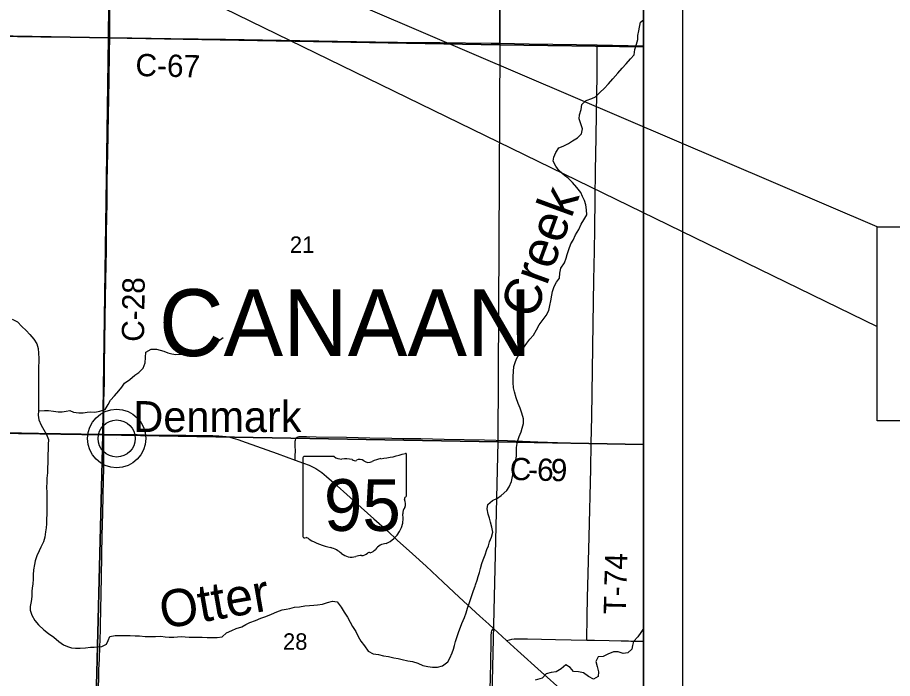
# Model space of a CAD drawing. Extents: x 0 to 45.9, y 0 to 22.
# Drawn here: x 7.305 to 9.535, y 15.053 to 16.738 of the extents above; entities that cross this region are included whole.
import ezdxf

# ---------------------------------------------------------------- set-up
doc = ezdxf.new("R2010")
doc.units = 0
for name, color, linetype in [('Default', 7, 'Continuous'), ('GM_X_County_Road', 7, 'Continuous'), ('GM_X_County_Road_Text', 7, 'Continuous'), ('GM_X_Minor_River', 7, 'Continuous'), ('GM_X_Minor_River_Text', 7, 'Continuous'), ('GM_X_Section', 7, 'Continuous'), ('GM_X_Section_Text', 7, 'Continuous'), ('GM_X_State_Location', 7, 'Continuous'), ('GM_X_State_Route', 7, 'Continuous'), ('GM_X_State_Shield', 7, 'Continuous'), ('GM_X_Township_Road', 7, 'Continuous'), ('GM_X_Township_Road_Text', 7, 'Continuous'), ('GM_X_Township_Text', 7, 'Continuous'), ('GM_X_Unincorporated', 7, 'Continuous'), ('GM_X_Unincorporated_Location', 7, 'Continuous'), ('GM_X_Unincorporated_Text', 7, 'Continuous'), ('SH_Border', 7, 'Continuous'), ('SH_Cut_Line', 7, 'Continuous'), ('SH_Text', 7, 'Continuous')]:
    doc.layers.add(name, color=color, linetype=linetype)

msp = doc.modelspace()

# ---------------------------------------------------------------- linework, layer by layer
at = {"layer": 'Default'}
msp.add_lwpolyline([(8.9, 14.1), (8.9, 19.7611)], dxfattribs=at)
for points in [[(8.9, 16.6634), (8.9, 17.6782), (8.5357, 17.6824), (8.5339, 16.6685)], [(8.9, 15.6495), (8.9, 16.6634), (8.5339, 16.6685), (8.5286, 15.6561)], [(8.9, 14.6398), (8.9, 15.6495), (8.5286, 15.6561), (8.5052, 14.6503)]]:
    msp.add_lwpolyline(points, close=True, dxfattribs=at)
at = {"layer": 'GM_X_County_Road'}
msp.add_line((8.7826, 16.6683), (8.9, 16.666), dxfattribs=at)
for points in [[(7.5398, 16.6872), (7.5398, 16.695), (7.5401, 16.7448), (7.5405, 16.7976), (7.5408, 16.8255), (7.5412, 16.8721), (7.5414, 16.925), (7.5417, 16.9716), (7.5421, 17.0244), (7.5424, 17.0648), (7.5425, 17.1145), (7.543, 17.1829), (7.5432, 17.2077), (7.5434, 17.2792), (7.5436, 17.3382), (7.5438, 17.3693), (7.5443, 17.4097), (7.5448, 17.4625), (7.5452, 17.5153), (7.5452, 17.5681), (7.5461, 17.6707), (7.5458, 17.698)], [(8.5341, 16.6724), (8.5341, 16.6809), (8.534, 16.7088), (8.5347, 16.8674), (8.5349, 16.9637), (8.5352, 17.116), (8.5351, 17.1813), (8.535, 17.2279), (8.5349, 17.259), (8.5356, 17.3305), (8.536, 17.4113), (8.5357, 17.4517), (8.536, 17.489), (8.536, 17.5885), (8.5363, 17.66), (8.536, 17.6836)], [(7.5244, 15.6756), (7.5244, 15.7009), (7.5247, 15.7226), (7.5251, 15.7537), (7.5259, 15.7879), (7.5263, 15.8034), (7.5267, 15.8469), (7.5274, 15.9121), (7.5282, 15.9681), (7.5291, 16.024), (7.5305, 16.1079), (7.5311, 16.142), (7.5315, 16.1886), (7.5325, 16.2292), (7.533, 16.2635), (7.5336, 16.3129), (7.5343, 16.3626), (7.5347, 16.3875), (7.536, 16.4434), (7.5385, 16.5784), (7.5393, 16.6484), (7.5398, 16.6872)], [(7.5398, 16.6872), (7.5959, 16.6865), (7.6953, 16.6846), (7.8351, 16.6823), (8.0246, 16.6791), (8.2171, 16.6756), (8.329, 16.6745), (8.3818, 16.6742), (8.5123, 16.6727), (8.5341, 16.6724)], [(8.5341, 16.6724), (8.6085, 16.6712), (8.7297, 16.6694), (8.7826, 16.6683)], [(7.5108, 15.0312), (7.5116, 15.0529), (7.5124, 15.0746), (7.5134, 15.1025), (7.5147, 15.1336), (7.5154, 15.1522), (7.5163, 15.1771), (7.5174, 15.2392), (7.5177, 15.2578), (7.5179, 15.2731), (7.5185, 15.3075), (7.52, 15.3696), (7.5208, 15.4162), (7.5221, 15.4752), (7.523, 15.5187), (7.5239, 15.5592), (7.524, 15.5692), (7.5243, 15.5772), (7.5244, 15.5832), (7.5246, 15.5924), (7.5247, 15.6048), (7.5249, 15.614), (7.525, 15.6265), (7.5249, 15.6389), (7.5248, 15.6516), (7.5244, 15.6729), (7.5244, 15.6756)], [(8.0121, 15.6096), (8.0122, 15.6109), (8.0126, 15.6189), (8.0128, 15.6234), (8.013, 15.6296), (8.0128, 15.6483), (8.0128, 15.6576), (8.0132, 15.6606), (8.0139, 15.6634), (8.0152, 15.6659), (8.0173, 15.6677), (8.0198, 15.669), (8.0227, 15.6695), (8.0257, 15.6698), (8.0288, 15.6698), (8.0411, 15.6693), (8.066, 15.6687), (8.1436, 15.6677), (8.2026, 15.6663), (8.2585, 15.6654), (8.2865, 15.6648), (8.3331, 15.6643), (8.3921, 15.663), (8.4946, 15.661), (8.5535, 15.659), (8.6311, 15.6562), (8.7056, 15.6536), (8.7672, 15.652)], [(8.7672, 15.652), (8.7709, 15.6519), (8.8143, 15.651), (8.9, 15.6492)], [(8.4956, 14.3977), (8.4962, 14.4285), (8.4974, 14.4999), (8.4987, 14.581), (8.4998, 14.6307), (8.5005, 14.6708), (8.502, 14.7364), (8.5034, 14.7858), (8.504, 14.8264), (8.5053, 14.876), (8.5057, 14.8978), (8.5063, 14.9199), (8.5073, 14.9473), (8.5078, 14.9752), (8.5085, 15.0033), (8.5099, 15.0527), (8.5109, 15.0966), (8.5118, 15.1429), (8.5119, 15.1617), (8.5129, 15.1706), (8.514, 15.1742), (8.5158, 15.1766), (8.5183, 15.1797)], [(8.5515, 15.1496), (8.5587, 15.1513), (8.5647, 15.1528), (8.5709, 15.1536), (8.5802, 15.1539), (8.6049, 15.1536), (8.6762, 15.1522), (8.7555, 15.1505)], [(8.7555, 15.1505), (8.7753, 15.15), (8.8125, 15.1494), (8.8435, 15.1488), (8.862, 15.1484), (8.8682, 15.1482), (8.8806, 15.1478), (8.8931, 15.1475), (8.9, 15.1474)]]:
    msp.add_lwpolyline(points, dxfattribs=at)
at = {"layer": 'GM_X_Minor_River'}
for points in [[(8.7426, 16.441), (8.7444, 16.4539), (8.7402, 16.4672), (8.7364, 16.4797), (8.7375, 16.4899), (8.7412, 16.5032), (8.7434, 16.5157), (8.7544, 16.5264), (8.7684, 16.531), (8.7783, 16.5356), (8.7896, 16.5477), (8.7998, 16.5565), (8.8108, 16.5687), (8.8225, 16.5816), (8.8353, 16.5957), (8.8459, 16.6086), (8.8561, 16.62), (8.8671, 16.6326), (8.8761, 16.6428), (8.8784, 16.6561), (8.8825, 16.6698), (8.8859, 16.6819), (8.8862, 16.6918), (8.8881, 16.7036), (8.8899, 16.713), (8.8929, 16.726), (8.9, 16.732)], [(8.4709, 15.2879), (8.472, 15.2917), (8.4761, 15.3035), (8.4787, 15.313), (8.4821, 15.3229), (8.4851, 15.3327), (8.4885, 15.3456), (8.4919, 15.3551), (8.4971, 15.368), (8.5009, 15.3813), (8.505, 15.3912), (8.508, 15.4007), (8.5125, 15.4132), (8.5159, 15.4257), (8.514, 15.4386), (8.5101, 15.4515), (8.5074, 15.4614), (8.5047, 15.4716), (8.502, 15.4849), (8.5031, 15.4962), (8.5152, 15.5065), (8.5281, 15.5126), (8.5379, 15.5195), (8.5516, 15.5317), (8.558, 15.5412), (8.5636, 15.5549), (8.5666, 15.5674), (8.5692, 15.5814), (8.5714, 15.5955), (8.5737, 15.6053), (8.5767, 15.6194), (8.5762, 15.6323), (8.5766, 15.6417), (8.5792, 15.6565), (8.5833, 15.6698), (8.5886, 15.6812), (8.5908, 15.6907), (8.5942, 15.7029), (8.5945, 15.7146), (8.5903, 15.729), (8.5857, 15.7415), (8.5811, 15.7536), (8.5758, 15.7684), (8.5712, 15.7836), (8.5688, 15.7938), (8.5677, 15.8071), (8.568, 15.823), (8.5687, 15.8355), (8.5702, 15.8484), (8.5732, 15.8583), (8.5765, 15.8678), (8.583, 15.8799), (8.5928, 15.8929), (8.6033, 15.9073), (8.6105, 15.9176), (8.6203, 15.9282), (8.6279, 15.9415), (8.6343, 15.9544), (8.6418, 15.9643), (8.6524, 15.978), (8.6592, 15.9906), (8.6618, 16.0035), (8.664, 16.0156), (8.6663, 16.03), (8.6681, 16.0395), (8.6726, 16.052), (8.6783, 16.0634), (8.6858, 16.0733), (8.6873, 16.0862), (8.6899, 16.0987), (8.6986, 16.1128), (8.7031, 16.1242), (8.7061, 16.1337), (8.7098, 16.1462), (8.7155, 16.1607), (8.7211, 16.1705), (8.7272, 16.1834), (8.7351, 16.1971), (8.7411, 16.2108), (8.7479, 16.2222), (8.7562, 16.2347), (8.755, 16.2476), (8.7534, 16.2601), (8.75, 16.2715), (8.745, 16.2814), (8.7404, 16.2916), (8.7305, 16.3041), (8.7191, 16.3169), (8.7084, 16.3279), (8.6989, 16.3351), (8.6856, 16.3471), (8.6769, 16.3589), (8.6704, 16.3717), (8.6718, 16.382), (8.6767, 16.3938), (8.6847, 16.4056), (8.6956, 16.4101), (8.7089, 16.4166), (8.7191, 16.4231), (8.732, 16.4307), (8.7426, 16.441)], [(7.2914, 15.9685), (7.3047, 15.9621), (7.3154, 15.95), (7.3264, 15.9395), (7.3363, 15.9296), (7.3462, 15.9179), (7.3542, 15.9062), (7.3577, 15.8944), (7.3581, 15.8819), (7.3589, 15.8683), (7.3589, 15.8588), (7.3586, 15.8489), (7.3583, 15.8357), (7.3583, 15.8262), (7.358, 15.8133), (7.358, 15.8034), (7.3584, 15.7939), (7.3584, 15.781), (7.3581, 15.7678), (7.3578, 15.7568), (7.3582, 15.7446), (7.3578, 15.7351), (7.3575, 15.7238), (7.3591, 15.7124), (7.3652, 15.6988), (7.3721, 15.6866), (7.3785, 15.6745), (7.3835, 15.662), (7.3832, 15.6488), (7.3829, 15.6362), (7.3821, 15.6237), (7.3822, 15.6021), (7.3815, 15.5896), (7.3812, 15.5767)], [(7.3578, 15.7351), (7.3738, 15.736), (7.3833, 15.7356), (7.3965, 15.7341), (7.4087, 15.7323), (7.4189, 15.7327), (7.4284, 15.7346), (7.4379, 15.7358), (7.4474, 15.732), (7.4607, 15.7298), (7.4717, 15.7302), (7.4823, 15.7318), (7.4918, 15.7322), (7.5016, 15.7318), (7.5149, 15.7342), (7.5282, 15.7388), (7.5357, 15.7513), (7.5417, 15.7623), (7.5516, 15.7737), (7.5629, 15.7863), (7.5704, 15.7958), (7.5772, 15.8053), (7.5912, 15.8152), (7.6037, 15.8262), (7.6136, 15.8327), (7.6253, 15.8438), (7.6305, 15.8578), (7.6312, 15.8707), (7.632, 15.8844), (7.6456, 15.8927), (7.6592, 15.8924), (7.6775, 15.8872), (7.6881, 15.8827), (7.698, 15.8804), (7.7086, 15.8789), (7.7215, 15.8793), (7.7367, 15.8821), (7.7496, 15.884), (7.7598, 15.884), (7.7723, 15.8852), (7.7825, 15.8883), (7.7924, 15.894), (7.8045, 15.9031), (7.8162, 15.9123), (7.8291, 15.9218)], [(7.3812, 15.5767), (7.3797, 15.5638), (7.3797, 15.5539), (7.379, 15.5388), (7.3791, 15.5289), (7.3791, 15.519), (7.3795, 15.5084), (7.3792, 15.4963), (7.3796, 15.4826), (7.3793, 15.4728), (7.3789, 15.458), (7.3786, 15.447), (7.3779, 15.4371), (7.3764, 15.4269), (7.3742, 15.4128), (7.3712, 15.4007), (7.3644, 15.3878), (7.3595, 15.3783), (7.3542, 15.3653), (7.3501, 15.3524), (7.3479, 15.3429), (7.3452, 15.33), (7.3445, 15.3168), (7.3446, 15.3065), (7.3439, 15.2933), (7.3424, 15.2838), (7.3413, 15.2743), (7.3409, 15.2614), (7.3391, 15.2485), (7.3369, 15.2363), (7.3373, 15.2265), (7.3415, 15.214), (7.3487, 15.2003), (7.3583, 15.1894), (7.3716, 15.1769), (7.3838, 15.1671), (7.3971, 15.158), (7.4104, 15.1467), (7.4222, 15.1388), (7.4317, 15.1339), (7.4427, 15.1305), (7.4522, 15.1298), (7.4647, 15.1298), (7.4783, 15.131), (7.4905, 15.1322), (7.5003, 15.1326), (7.5098, 15.133), (7.5193, 15.1342), (7.5318, 15.1403), (7.5359, 15.1498), (7.5397, 15.1593), (7.5533, 15.1624), (7.5917, 15.1625), (7.6046, 15.1614), (7.6156, 15.1614), (7.6304, 15.1596), (7.6433, 15.1596), (7.6565, 15.16), (7.6702, 15.1601), (7.6808, 15.1586), (7.6911, 15.1583), (7.7032, 15.1583), (7.7127, 15.1587), (7.7222, 15.1595), (7.7324, 15.1588), (7.7419, 15.1581), (7.7544, 15.1577), (7.7756, 15.1578), (7.7885, 15.1575), (7.8018, 15.1575), (7.814, 15.1568), (7.8265, 15.1587), (7.8374, 15.1694), (7.8511, 15.1747), (7.8624, 15.1797), (7.8761, 15.1843), (7.8863, 15.19), (7.8969, 15.1954), (7.9117, 15.2007), (7.9253, 15.2061), (7.9378, 15.2103), (7.9518, 15.2168), (7.9655, 15.2229), (7.9791, 15.2275), (7.9893, 15.2294), (7.9992, 15.2314), (8.0109, 15.2344), (8.0238, 15.2352), (8.0371, 15.2375), (8.0492, 15.2391), (8.0598, 15.2395), (8.0693, 15.2403), (8.0822, 15.2419), (8.0947, 15.2461), (8.1072, 15.2499), (8.1194, 15.2481), (8.1293, 15.2348), (8.1369, 15.222), (8.1457, 15.2091), (8.1529, 15.1966), (8.1587, 15.1849)], [(8.1587, 15.1849), (8.1667, 15.1727), (8.1732, 15.1595), (8.18, 15.1474), (8.1888, 15.1357), (8.1987, 15.1224), (8.2116, 15.1153), (8.2249, 15.1134), (8.2378, 15.1108), (8.2504, 15.1086), (8.2636, 15.1052), (8.2746, 15.1037), (8.2849, 15.1011), (8.2997, 15.0973), (8.3118, 15.0959), (8.3248, 15.0917), (8.3381, 15.0857), (8.3502, 15.0835), (8.3627, 15.0812), (8.3756, 15.0813), (8.3881, 15.0851), (8.4014, 15.095), (8.407, 15.1045), (8.4127, 15.1178), (8.4161, 15.1273), (8.4183, 15.1368), (8.4209, 15.1467), (8.4254, 15.1596), (8.4295, 15.1725), (8.4337, 15.1831), (8.4371, 15.1926), (8.4438, 15.2078), (8.4483, 15.22), (8.4517, 15.2321), (8.4547, 15.2416), (8.4581, 15.2515), (8.463, 15.264), (8.4671, 15.2773), (8.4709, 15.2879)], [(8.9, 15.18), (8.8999, 15.1797), (8.8931, 15.1699), (8.8859, 15.1585), (8.875, 15.147), (8.8723, 15.1368), (8.8705, 15.1273), (8.8607, 15.1178), (8.8481, 15.1166), (8.836, 15.1207), (8.8235, 15.1207), (8.8098, 15.1146), (8.7977, 15.1085), (8.7844, 15.1077), (8.7788, 15.0959), (8.7826, 15.0834), (8.7857, 15.0698), (8.785, 15.058), (8.7725, 15.0507), (8.7603, 15.0575), (8.747, 15.0673), (8.7345, 15.0692), (8.7216, 15.0707), (8.7136, 15.0809), (8.7022, 15.0877), (8.6901, 15.0774), (8.6776, 15.0694), (8.6647, 15.0675), (8.6522, 15.0644), (8.6416, 15.0533), (8.6242, 15.0484)]]:
    msp.add_lwpolyline(points, dxfattribs=at)
at = {"layer": 'GM_X_Section'}
for points in [[(6.5217, 17.7114), (7.5472, 17.6966), (7.5363, 16.6862), (6.5134, 16.7036)], [(7.5472, 17.6966), (8.5357, 17.6824), (8.5339, 16.6685), (7.5363, 16.6862)], [(6.5134, 16.7036), (7.5363, 16.6862), (7.5224, 15.6742), (6.5014, 15.6897)], [(7.5363, 16.6862), (8.5339, 16.6685), (8.5286, 15.6561), (7.5224, 15.6742)], [(7.5224, 15.6742), (7.4967, 14.6639), (6.4893, 14.6816), (6.5014, 15.6897)], [(8.5286, 15.6561), (8.5052, 14.6503), (7.4967, 14.6639), (7.5224, 15.6742)]]:
    msp.add_lwpolyline(points, close=True, dxfattribs=at)
at = {"layer": 'GM_X_State_Route'}
for points in [[(7.2725, 15.6795), (7.3586, 15.6779), (7.4145, 15.677), (7.4334, 15.6767)], [(7.4334, 15.6767), (7.4673, 15.6762), (7.5232, 15.6756), (7.5244, 15.6756), (7.5853, 15.6748), (7.5917, 15.6748), (7.5975, 15.6746), (7.6098, 15.6743), (7.6315, 15.6741), (7.6874, 15.6732), (7.734, 15.6726), (7.8024, 15.6719), (7.8179, 15.6714), (7.8273, 15.6707), (7.8365, 15.6694), (7.8458, 15.6676), (7.8548, 15.6653), (7.8667, 15.6616), (7.8873, 15.6544), (7.9662, 15.626), (8.0121, 15.6096), (8.0335, 15.6019), (8.0481, 15.5963), (8.0567, 15.5926), (8.0649, 15.5881), (8.0728, 15.583), (8.0804, 15.5775), (8.0925, 15.5677), (8.1112, 15.5513), (8.1526, 15.5137), (8.1805, 15.4889), (8.2128, 15.4598), (8.2475, 15.4287), (8.2728, 15.4057), (8.3119, 15.3702), (8.3462, 15.3386), (8.3608, 15.325)], [(8.3608, 15.325), (8.3893, 15.2983), (8.4304, 15.2603), (8.4829, 15.2119), (8.5059, 15.1909), (8.5183, 15.1797), (8.5515, 15.1496), (8.5795, 15.1241), (8.6395, 15.07), (8.6949, 15.0201), (8.7395, 14.9798)]]:
    msp.add_lwpolyline(points, dxfattribs=at)
at = {"layer": 'GM_X_State_Shield'}
for p, q in [((8.0323, 15.6149), (8.0323, 15.4148)), ((8.1121, 15.6184), (8.0349, 15.6184)), ((8.296, 15.5186), (8.296, 15.6233)), ((8.296, 15.5187), (8.296, 15.5186))]:
    msp.add_line(p, q, dxfattribs=at)
for centre, radius, start, end in [((8.0353, 15.6154), 0.00305, 98.1301, 188.1301), ((8.1305, 15.6416), 0.0296, 231.6195, 271.1119), ((8.1403, 15.506), 0.1064, 80.4867, 94.9883), ((8.2377, 15.5573), 0.0563, 97.3462, 120.7689), ((8.2021, 15.8912), 0.2796, 275.8445, 288.9065), ((8.2931, 15.6238), 0.00294, 351.8621, 97.738), ((8.1645, 15.6164), 0.00855, 219.7921, 297.1024), ((8.177, 15.5933), 0.0178, 54.4667, 119.1411), ((8.2, 15.625), 0.0214, 233.8562, 294.8282), ((8.2953, 15.511), 0.00454, 107.944, 210.337), ((8.2664, 15.4977), 0.0273, 340.033, 23.6496), ((8.2928, 15.5182), 0.00314, 289.6038, 7.7341), ((8.3065, 15.4748), 0.0198, 136.8065, 186.9296), ((8.2177, 15.4615), 0.0699, 292.3089, 8.9858), ((8.0354, 15.4144), 0.00308, 171.9584, 258.3066), ((8.0358, 15.4348), 0.0235, 267.339, 280.6039), ((8.0406, 15.4033), 0.00848, 29.7484, 93.2717), ((8.1477, 15.5831), 0.2019, 240.4129, 257.1985), ((8.2472, 15.3586), 0.0383, 94.4031, 142.5768), ((8.0875, 15.3249), 0.0632, 47.1842, 75.836), ((8.1558, 15.4023), 0.0401, 230.7004, 286.2918), ((8.1819, 15.3873), 0.0214, 268.777, 315.5493), ((8.2012, 15.3679), 0.00601, 65.7517, 132.6484), ((8.1987, 15.3954), 0.0226, 282.8732, 323.2771), ((8.179, 15.3331), 0.0329, 85.6951, 111.2099)]:
    msp.add_arc(centre, radius, start, end, dxfattribs=at)
at = {"layer": 'GM_X_Township_Road'}
for points in [[(6.5172, 16.7037), (6.5315, 16.7034), (6.5906, 16.7026), (6.6682, 16.7007), (6.8174, 16.6975), (6.9758, 16.6945), (7.184, 16.6915), (7.3642, 16.689), (7.4574, 16.6876), (7.5369, 16.6872), (7.5398, 16.6872)], [(8.7672, 15.652), (8.7686, 15.7209), (8.772, 15.9568), (8.7738, 16.0685), (8.775, 16.143), (8.776, 16.1989), (8.777, 16.2765), (8.7782, 16.3479), (8.7793, 16.4317), (8.7802, 16.4938), (8.7818, 16.59), (8.7825, 16.6583), (8.7826, 16.6683)], [(8.7555, 15.1505), (8.7567, 15.2119), (8.7577, 15.2585), (8.7615, 15.4136), (8.7659, 15.5874), (8.7672, 15.652)]]:
    msp.add_lwpolyline(points, dxfattribs=at)
at = {"layer": 'GM_X_Unincorporated'}
for radius in [0.0744, 0.0472]:
    msp.add_circle((7.5574, 15.6645), radius, dxfattribs=at)
at = {"layer": 'GM_X_Unincorporated_Location'}
msp.add_line((7.5574, 15.6645), (7.5574, 15.6645), dxfattribs=at)
at = {"layer": 'SH_Border'}
for points in [[(9.4963, 16.2045), (5.2331, 18.0284), (9.4963, 15.9502)], [(9.4963, 16.2045), (10.9954, 16.2045), (10.9954, 15.7097), (9.4963, 15.7097)]]:
    msp.add_lwpolyline(points, close=True, dxfattribs=at)
at = {"layer": 'SH_Cut_Line'}
for p, q in [((9, 21), (9, 14)), ((8.9, 20.9), (8.9, 14.1))]:
    msp.add_line(p, q, dxfattribs=at)
at = {"layer": 'SH_Text'}
msp.add_lwpolyline([(8.9, 14.1), (8.9, 19.7611)], dxfattribs=at)

# ---------------------------------------------------------------- texts
at = {"layer": 'GM_X_County_Road_Text'}
for s, height, rotation, p in [('C-67', 0.05682, 358.6285, (7.6049, 16.5888)), ('C-28', 0.05682, 89.3202, (7.6272, 15.9109)), ('C', 0.0568, 358.4935, (8.559, 15.559)), ('6', 0.0568, 358.4981, (8.6284, 15.5571)), ('9', 0.0568, 358.5178, (8.6632, 15.5562)), ('-', 0.0568, 358.4937, (8.6053, 15.5578))]:
    msp.add_text(s, height=height, rotation=rotation, dxfattribs=at).set_placement(p)
at = {"layer": 'GM_X_Minor_River_Text'}
for s, height, rotation, p in [('Creek', 0.09472, 69.9727, (8.6222, 15.9662)), ('Otter', 0.09471, 9.9753, (7.6755, 15.1785))]:
    msp.add_text(s, height=height, rotation=rotation, dxfattribs=at).set_placement(p)
at = {"layer": 'GM_X_Section_Text'}
for s, p in [('21', (7.9989, 16.1379)), ('28', (7.9814, 15.1259))]:
    msp.add_text(s, height=0.04186, rotation=0, dxfattribs=at).set_placement(p)
at = {"layer": 'GM_X_State_Location'}
for s in ['s', 'r']:
    msp.add_text(s, height=0.000189, dxfattribs=at).set_placement((8.1612, 15.5016))
msp.add_text('95', height=0.000189, rotation=0, dxfattribs=at).set_placement((8.1135, 15.4878))
at = {"layer": 'GM_X_State_Shield'}
msp.add_text('95', height=0.13184, dxfattribs=at).set_placement((8.0856, 15.4289))
at = {"layer": 'GM_X_Township_Road_Text'}
msp.add_text('T-74', height=0.05682, rotation=88.5837, dxfattribs=at).set_placement((8.8554, 15.2154))
at = {"layer": 'GM_X_Township_Text'}
msp.add_text('CANAAN', height=0.17045, rotation=0, dxfattribs=at).set_placement((7.6652, 15.8746))
at = {"layer": 'GM_X_Unincorporated_Text'}
msp.add_text('Denmark', height=0.07898, rotation=0, dxfattribs=at).set_placement((7.6001, 15.6808))

doc.saveas('drawing.dxf')
